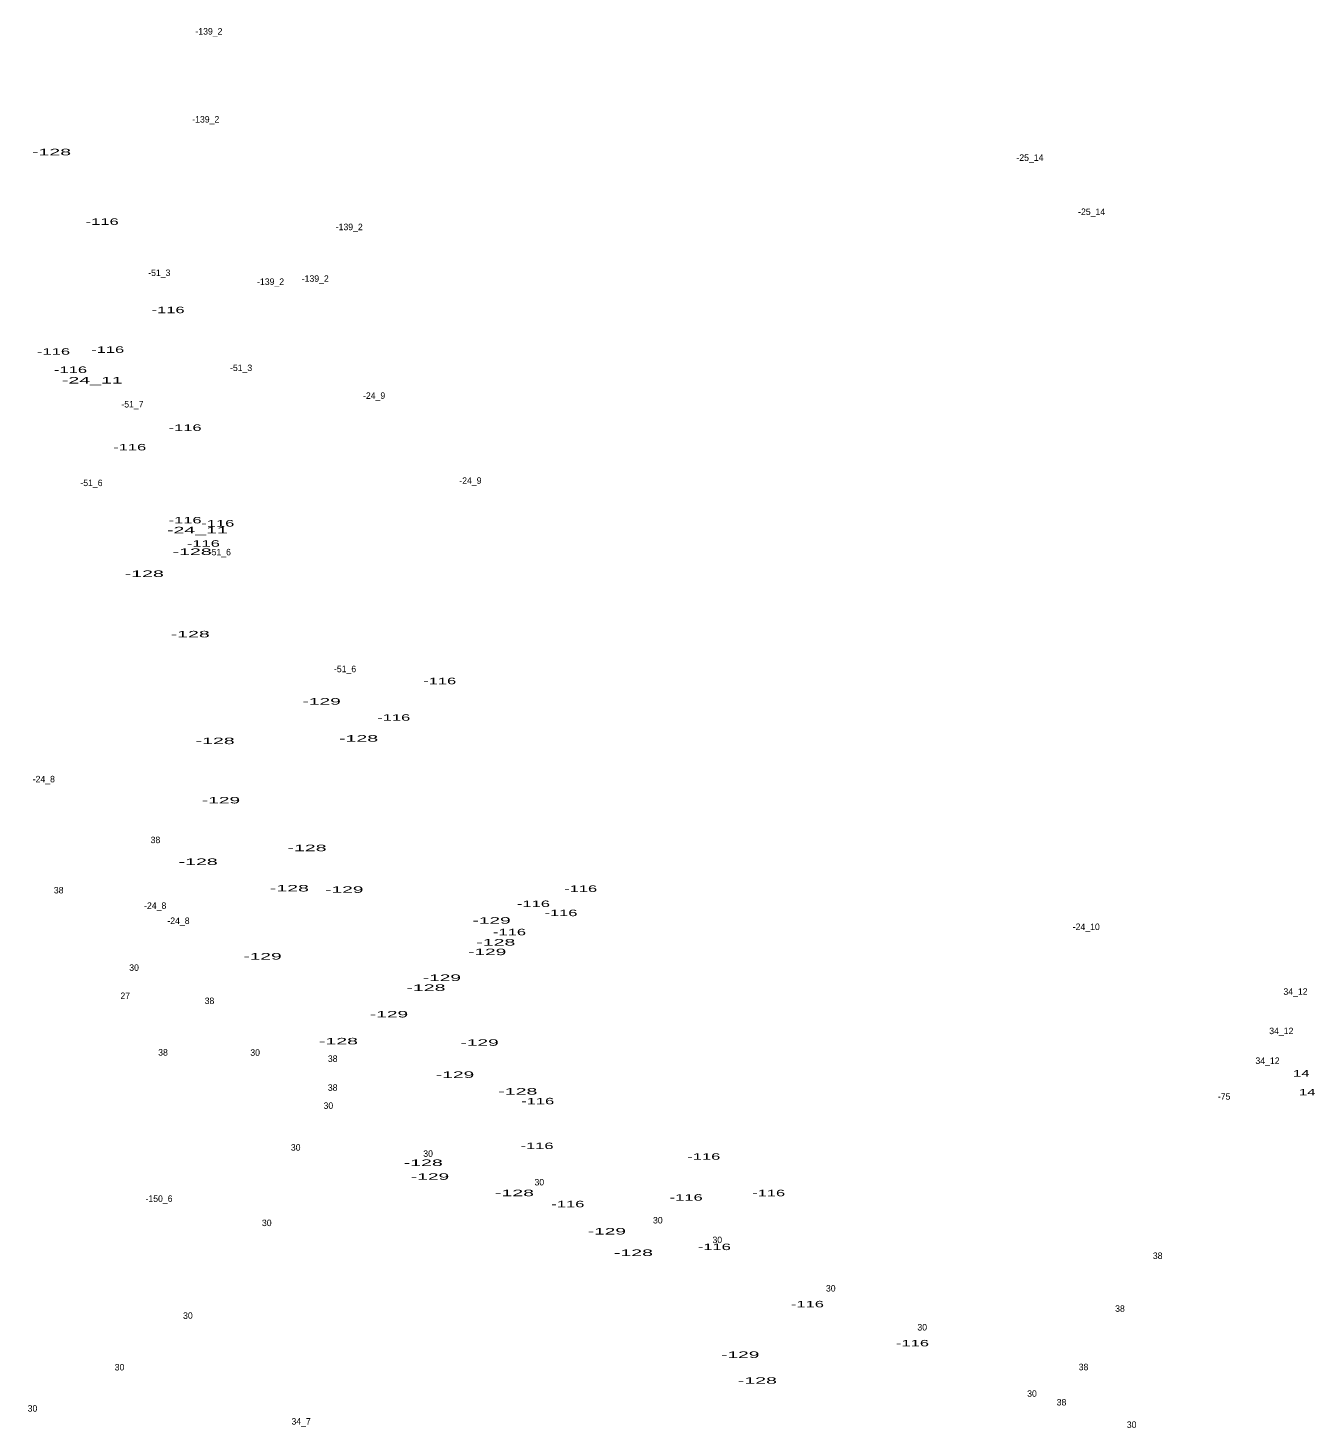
# Model space of a CAD drawing. Extents: x -662499 to -659675, y -1001682 to -998165.
# Drawn here: x -662084 to -661291, y -999936 to -999074 of the extents above; entities that cross this region are included whole.
import ezdxf
from ezdxf.enums import TextEntityAlignment as Align

# ---------------------------------------------------------------- set-up
doc = ezdxf.new("R2010")
doc.units = 0
doc.header["$LTSCALE"] = 1.6
doc.layers.add('24', color=7, linetype='Continuous')

msp = doc.modelspace()

# ---------------------------------------------------------------- texts
at = {"layer": '24'}
for s, p in [('-139_2', (-661972.042, -999077.57)), ('-139_2', (-661973.982, -999131.77)), ('-25_14', (-661466.15, -999155.38)), ('-25_14', (-661428.15, -999188.74)), ('-139_2', (-661885.582, -999198.1)), ('-51_3', (-662002.606, -999226.35)), ('-139_2', (-661934.042, -999231.84)), ('-139_2', (-661906.522, -999229.9)), ('-51_3', (-661952.206, -999284.92)), ('-24_9', (-661870.242, -999302.04)), ('-51_7', (-662019.152, -999307.35)), ('-24_9', (-661810.912, -999354.4)), ('-51_6', (-662044.412, -999355.8)), ('-51_6', (-661965.312, -999398.47)), ('-51_6', (-661888.152, -999470.48)), ('-24_8', (-662073.767, -999538.36)), ('38', (-662004.977, -999575.81)), ('38', (-662064.617, -999606.8)), ('-24_8', (-662005.137, -999616.33)), ('-24_8', (-661990.787, -999625.64)), ('-24_10', (-661431.444, -999629.35)), ('30', (-662018.151, -999654.5)), ('27', (-662023.583, -999671.87)), ('34_12', (-661302.533, -999669.28)), ('38', (-661971.677, -999674.98)), ('34_12', (-661311.253, -999693.49)), ('38', (-662000.327, -999706.75)), ('30', (-661943.561, -999706.84)), ('38', (-661895.767, -999710.62)), ('34_12', (-661319.773, -999711.9)), ('38', (-661895.767, -999728.44)), ('-75', (-661346.511, -999733.91)), ('30', (-661898.441, -999739.58)), ('30', (-661918.571, -999765.31)), ('30', (-661836.981, -999769.11)), ('30', (-661768.441, -999786.74)), ('-150_6', (-662002.786, -999796.88)), ('30', (-661695.441, -999810.18)), ('30', (-661936.391, -999811.8)), ('30', (-661658.781, -999822.29)), ('38', (-661387.447, -999832.07)), ('30', (-661588.881, -999852.12)), ('30', (-661984.991, -999868.95)), ('38', (-661410.677, -999864.61)), ('30', (-661532.531, -999876.14)), ('30', (-662027.111, -999900.76)), ('38', (-661433.137, -999900.64)), ('30', (-661464.881, -999916.99)), ('38', (-661446.697, -999922.33)), ('30', (-662080.741, -999926.14)), ('34_7', (-661915.235, -999934.14)), ('30', (-661403.501, -999936.16))]:
    msp.add_text(s, height=4, dxfattribs=at).set_placement(p, align=Align.CENTER)
for s, width, p in [('-128', 2.25, (-662069.011, -999151.95)), ('-116', 1.9, (-662037.791, -999194.82)), ('-116', 1.9, (-661997.191, -999249.25)), ('-116', 1.9, (-662067.761, -999274.85)), ('-116', 1.9, (-662034.421, -999273.69)), ('-116', 1.9, (-662057.291, -999286.1)), ('-24_11', 2.25, (-662043.893, -999292.59)), ('-116', 1.9, (-661986.721, -999321.78)), ('-116', 1.9, (-662020.841, -999333.81)), ('-116', 1.9, (-661986.721, -999378.8)), ('-24_11', 2.25, (-661979.143, -999384.9)), ('-116', 1.9, (-661966.561, -999380.74)), ('-116', 1.9, (-661975.481, -999393.15)), ('-128', 2.25, (-661982.391, -999398.21)), ('-128', 2.25, (-662011.861, -999411.79)), ('-128', 2.25, (-661983.561, -999449.02)), ('-116', 1.9, (-661829.841, -999477.88)), ('-129', 2.2, (-661902.565, -999490.46)), ('-116', 1.9, (-661858.151, -999500.38)), ('-128', 2.25, (-661968.201, -999514.8)), ('-128', 2.25, (-661879.801, -999513.27)), ('-129', 2.2, (-661964.605, -999551.35)), ('-128', 2.25, (-661911.591, -999580.77)), ('-128', 2.25, (-661978.671, -999589.27)), ('-128', 2.25, (-661922.451, -999605.59)), ('-129', 2.2, (-661888.605, -999606.43)), ('-116', 1.9, (-661742.991, -999605.86)), ('-116', 1.9, (-661772.071, -999615.19)), ('-116', 1.9, (-661755.131, -999620.81)), ('-129', 2.2, (-661797.875, -999625.44)), ('-128', 2.25, (-661795.271, -999638.92)), ('-116', 1.9, (-661786.811, -999632.62)), ('-129', 2.2, (-661939.015, -999647.55)), ('-129', 2.2, (-661800.595, -999644.83)), ('-129', 2.2, (-661828.505, -999660.73)), ('-128', 2.25, (-661838.311, -999666.85)), ('-129', 2.2, (-661861.075, -999683.23)), ('-128', 2.25, (-661892.211, -999699.82)), ('-129', 2.2, (-661805.245, -999700.69)), ('-129', 2.2, (-661820.365, -999720.47)), ('14', 1.7, (-661298.983, -999719.66)), ('-128', 2.25, (-661781.701, -999730.77)), ('14', 1.7, (-661295.303, -999731.28)), ('-116', 1.9, (-661769.471, -999736.79)), ('-116', 1.9, (-661769.861, -999764.33)), ('-128', 2.25, (-661839.981, -999774.75)), ('-116', 1.9, (-661667.111, -999770.92)), ('-129', 2.2, (-661835.795, -999783.26)), ('-128', 2.25, (-661783.751, -999793.36)), ('-116', 1.9, (-661627.171, -999793.42)), ('-116', 1.9, (-661750.861, -999800.22)), ('-116', 1.9, (-661677.971, -999796.13)), ('-129', 2.2, (-661726.845, -999817)), ('-116', 1.9, (-661660.641, -999826.59)), ('-128', 2.25, (-661710.471, -999830.21)), ('-116', 1.9, (-661603.251, -999861.89)), ('-116', 1.9, (-661538.501, -999885.94)), ('-129', 2.2, (-661644.645, -999893.03)), ('-128', 2.25, (-661634.091, -999908.95))]:
    msp.add_text(s, height=4, dxfattribs=dict(at, width=width)).set_placement(p, align=Align.CENTER)

doc.saveas('drawing.dxf')
